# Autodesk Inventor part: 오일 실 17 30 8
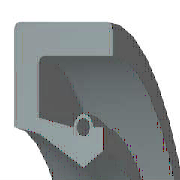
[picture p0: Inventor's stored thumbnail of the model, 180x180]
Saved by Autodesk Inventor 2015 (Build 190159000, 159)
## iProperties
IsCustomPart: 1
Created: 2012-02
Part Number: 오일 실 17 30 8
Material: 고무
Description: 오일-실
Document SubType Name: Modeling
Standard: KS B 2804
Designer: mduedu
Standards Organization: KS
Language: ko-KR
Size Designation: S - 17 30 8
Categories: <MemberInstance><Categories><Category DisplayName="샤프트 부품" InternalName="7f7aeb1f-a693-4053-b835-cee3144e0d98" Mnemonic="SHFT"><Category DisplayName="실링" Intern
Density: 0.93 g/cm^3
Appearance: 고무 - 검은색 - 버전 1.1
Author: mduedu
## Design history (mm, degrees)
revolve "본체" stored, may be unused: angle "d17" = 90 deg
revolve "스프링1" stored, may be unused: angle "d18" = 90 deg
body "Solid1"
sketch "스케치1"
  geometry: L1 (0, 15)-(8, 15); L2 (8, 15)-(8, 13.75); L3 (8, 13.75)-(1.75, 13.75); L4 (0, 15)-(0, 10.6); L5 (0, 10.6)-(1.75, 10.25); L6 (1.75, 10.25)-(4.9, 8.5); L7 (4.9, 8.5)-(0, 8.5); L8 (6.3, 9.375)-(6.3, 10.6); L9 (0, 0)-(9.586, 0) reference; L10 (4.9, 8.5)-(6.3, 9.375); L11 (0, 18)-(0, -3) reference; L12 (-1.917, 0)-(11.503, 0) reference; L13 (4.2, 10.6)-(1.75, 11.09); L14 (1.75, 11.09)-(1.75, 13.75); L15 (6.3, 10.6)-(5.6, 10.6); C1 r 0.455 at (4.9, 10.6); A1 r 0.7 centre (4.9, 10.6) between (5.6, 10.6) and (4.2, 10.6)
  constraints: 26 end point, 5 horizontal alignment, 4 perpendicular, 2 centre point, 2 collinear, 2 horizontal, 2 parallel, 2 point on circle, 2 point on line, 2 vertical alignment, 1 coincident
  dimensions: "d0" = 30 diameter of L1 L9 (= SD2); "d1" = 18.75 diameter of L8.start L9 (= ABDM); "d2" = 1.25 distance of L1.end L2.end (computed from SD); "d3" = 0.91 diameter of C1 (= SPDI); "d4" = 1.4 diameter of A1 (= SPDA); "d5" = 17 diameter of L6.end L9 (= NND); "d6" = 20.5 diameter of L5.end L9 (= TKDM); "d7" = 21.2 diameter of L4.end L9 (= HLDM); "d8" = 4.9 distance from line of C1.centre L4 (= SPDST); "d9" = 6.3 distance between parallel lines of L8 L4 (= SDI); "d10" = 8 distance between parallel lines of L2 L4 (= SWDT); "d12" = 1.75 distance between parallel lines of L14 L4 (= SD)
fillet "모깎기1" dims "d11" = 0.5 (= RR)
other parameters: "SD2" = 30 [user parameter; used in 1 equation term], "SWDT" = 8 [user parameter; used in 1 equation term], "RR" = 0.5 [user parameter; used in 1 equation term], "SD" = 1.75 [user parameter; used in 2 equation terms], "NND" = 17 [user parameter; used in 1 equation term], "SPDA" = 1.4 [user parameter; used in 1 equation term], "SPDI" = 0.91 [user parameter; used in 1 equation term], "TKDM" = 20.5 [user parameter; used in 1 equation term], "HLDM" = 21.2 [user parameter; used in 1 equation term], "ABDM" = 18.75 [user parameter; used in 1 equation term], "SDI" = 6.3 [user parameter; used in 1 equation term], "SPDST" = 4.9 [user parameter; used in 1 equation term], "d13" = 0, "d14" = 0, "d15" = 0, "LAB" = 0.35 [user parameter]
